(* Logix 5000 project; controller SpectraLink_Test_v2 vendor 1 type 14 code 92 rev 36.12; software revision 36.00 *)

TASK MainTask (continuous, watchdog 500 ms) : MainProgram

MODULES
   Local : vendor 1 type 14 code 92 (ICP 0, rev 36.12)
      ENBT : 1756-ENBT (ICP 1, Ethernet 192.168.3.50, rev 6.1)
         SpectraLink : ETHERNET-MODULE (Ethernet 192.168.3.1, rev 1.1, Output RPI 20 ms)
END_MODULES

TYPE DUT_NDSN_spLink :   // UDDT that holds the Cyclic and ACyclic data for the SpectraLink.
STRUCT
   b_r_LostComm : BOOL;
   b_r_PLC_CommReadOnly : BOOL;
   b_r_SystemReady : BOOL;   // Pattern Status Word 0 Bit 0
   b_r_Fault : BOOL;   // Pattern Status Word 0 Bit 1
   b_r_Alert : BOOL;   // Pattern Status Word 0 Bit 2
   b_r_Commissioned : BOOL;   // Pattern Status Word 0 Bit 3
   b_r_RecipeModified : BOOL;   // Pattern Status Word 0 Bit 5
   i_r_Recipe : INT;
   i_r_PalletizedCount : INT;
   i_r_PalletizedSkipCount : INT;
   di_r_App_Trig_ProductCount : DINT;
   di_r_FeedCount : DINT;
   di_r_DeliveryCount : DINT;
   st_r_AppStat : DUT_NDSN_spLink_Chan_Status[8];
   st_r_TrigStat : DUT_NDSN_spLink_Trig_Status[8];
   st_r_EncoStat : DUT_NDSN_spLink_Encoder_Status[8];
   i_r_ProductLength : DINT[8];
   i_r_ProdRate : INT;
   i_r_LineSpeed : INT[2];   // m/min units
   i_r_RunupOutput : INT[2];
   b_w_UnitEnable : BOOL;   // Pattern Control Word 0 Bit 0
   b_w_ClearAllAlarms : BOOL;   // Clear all System Faults and Alerts (Rising Edge).
   b_w_ResetAllCounters : BOOL;   // Reset all counters (rising edge).
   i_w_LoadRecipe : INT;
   i_w_PalletizedCount : INT;   // Write 0 to decrement; 1 to increment; 2 to reset; else does nothing.
   i_w_PalletizedSkipCount : INT;   // Write 0 to decrement; 1 to increment; 2 to reset; else does nothing.
   di_w_App_Trig_ProductCount : DINT;
   di_w_FeedCountReset : DINT;
   di_w_DeliveryCountReset : DINT;
   st_w_AppCtl : DUT_NDSN_spLink_Chan_CTL[8];
   st_rw_BeadAgg : DUT_NDSN_spLink_Bead[8];
   i_rw_RnUpPercentOutP1 : INT[2];
   i_rw_RnUpLineSpdP1 : INT[2];
   i_rw_RnUpPercentOutP2 : INT[2];
   i_rw_RnUpLineSpdP2 : INT[2];
   i_rw_RnUpLowLim : INT[2];
   i_rw_RnUpHighLim : INT[2];
   di_rw_EncoderRes : DINT[2];
   i_rw_TriggerMaskDist : DINT[8];
   i_rw_TriggerChCtl : INT[8];
   i_rw_EncoderChCtl : INT[2];
   i_rw_RandAdjStart : INT[8];
   i_rw_RandAdjEnd : INT[8];
   i_rw_VirtualTriggerSize : DINT[8];
   i_rw_ContStartSpeed : INT[8];
   i_rw_ContStopSpeed : INT[8];
   i_rw_ContKnifeCutDelay : DINT[8];
   i_rw_ContKnifeCutGap : DINT[8];
   di_rw_GTO : DINT[8];
   i_r_ErrorInfo : INT[4];
   i_r_SpecCtl : INT[4];
   i_r_CurrentFault : INT;
END_STRUCT
END_TYPE

TYPE DUT_NDSN_spLink_Bead :
STRUCT
   di_rw_NumOfBeads : DINT;
   di_rw_BeadDelay : DINT[8];   // 1/4 mm
   di_rw_BeadDuration : DINT[8];   // 1/4 mm
   di_rw_mode : DINT;   // 1/4 mm
   di_rw_MaxGunTime : DINT;   // microseconds
   di_rw_LineSpeedActivation : DINT;   // 100th m/min
   di_rw_LineSpeedDeactivation : DINT;   // 100th m/min
   di_rw_Interval : DINT;   // 1/4 mm
   di_rw_AdhesiveSavings : DINT;   // 30%-60%
   di_rw_EcoBeadPattern : DINT;   // 0-40, Illegal values: 0,1,11,20,21,30,31,38,39
END_STRUCT
END_TYPE

TYPE DUT_NDSN_spLink_Chan_CTL :
STRUCT
   b_w_Enable : BOOL;
   b_w_Purge : BOOL;
END_STRUCT
END_TYPE

TYPE DUT_NDSN_spLink_Chan_Status :
STRUCT
   b_r_Enabled : BOOL;
   b_r_Fault : BOOL;
   b_r_Alert : BOOL;
   b_r_Output_Active : BOOL;
   b_r_Installed : BOOL;
END_STRUCT
END_TYPE

TYPE DUT_NDSN_spLink_Encoder_Status :   // SpectraLink Encoder Channel Status
STRUCT
   b_r_Missing : BOOL;
   b_r_Phase_Missing : BOOL;
   b_r_Scaled : BOOL;
   b_r_Fault : BOOL;
   b_r_Alert : BOOL;
   b_r_Installed : BOOL;
END_STRUCT
END_TYPE

TYPE DUT_NDSN_spLink_HMI_Data :
STRUCT
   r_w_RunUp_1_P1_LineSpeed : REAL;
   r_w_RunUp_2_P1_LineSpeed : REAL;
   r_w_RunUp_1_P2_LineSpeed : REAL;
   r_w_RunUp_2_P2_LineSpeed : REAL;
   r_tempstorage : REAL[4];
   i_tempstorage : INT[4];
END_STRUCT
END_TYPE

TYPE DUT_NDSN_spLink_Rd_Wt :
STRUCT
   i_arr_ReadValue : INT[60];
   i_ReadADI : INT;
   b_ReadDone : BOOL;
   i_arr_WriteValue : INT[60];
   i_WriteADI : INT;
   i_WriteSizeBytes : INT;
   b_WriteEvent : BOOL;
   b_WriteDone : BOOL;
   b_FirstScan : BOOL;
   b_AllowWrites : BOOL;
   b_WriteErr : BOOL;
   b_ReadErr : BOOL;
END_STRUCT
END_TYPE

TYPE DUT_NDSN_spLink_Trig_Status :   // SpectraLink Trigger Channel Status
STRUCT
   b_r_Detected : BOOL;
   b_r_Fault : BOOL;
   b_r_Alert : BOOL;
   b_r_Active : BOOL;
   b_r_Installed : BOOL;
END_STRUCT
END_TYPE

TYPE DUT_spLink_ADI :
STRUCT
   i_ADI : INT;
   i_Size : INT;
END_STRUCT
END_TYPE

ADD_ON_INSTRUCTION AOI_Add_Quad_Resolution   (* revision 1.0 *)
// Raw data from the SpectraLink has a x4 factor included for resolution.  This ADI adds that factor for the SpectraLink.
VAR_IN_OUT
   Bead_Agg : DUT_NDSN_spLink_Bead; {required}
END_VAR
VAR_INPUT
   i_Counter : INT; {access Read Only}
END_VAR

ROUTINE Logic   (* structured text *)
// Raw data from the SpectraLink has a x4 factor included for resolution.  This ADI removes that factor to make editing easier.
   //
   //
   
   FOR i_Counter := 0 TO 7 DO
   
   	Bead_Agg.di_rw_BeadDelay[i_Counter] := Bead_Agg.di_rw_BeadDelay[i_Counter]*4;
   	Bead_Agg.di_rw_BeadDuration[i_Counter] := Bead_Agg.di_rw_BeadDuration[i_Counter]*4;
   
   END_FOR;
END_ROUTINE
END_ADD_ON_INSTRUCTION

ADD_ON_INSTRUCTION AOI_Bead_Calculate_Limits   (* revision 1.0 *)
VAR_IN_OUT
   UDDT1 : DUT_NDSN_spLink_Bead; {required}
   di_DelayHi : DINT[8]; {required}
   di_DelayLo : DINT[8]; {required}
   di_DurHi : DINT[8]; {required}
   di_DurLo : DINT[8]; {required}
END_VAR
VAR_INPUT
   b_time_distance_Mode : BOOL; {access Read Only, required}   // Time
END_VAR
VAR_IN_OUT
   i_DotIntervalHi : DINT; {required}
   i_DotIntervalLo : DINT; {required}
END_VAR
VAR
   Max_Hi_Limit : DINT; {access None}
   i_Counter : INT; {access None}
   i_BeadTemp : INT; {access None}
   DotIntHiLimit : INT; {access None}
   DotIntLoLimit : INT; {access None}
END_VAR

ROUTINE Logic   (* structured text *)
   //****************************************************************************************
   //
   //  Subroutine:  Bead_Calculate_Limits
   //
   //  Function:  Calculate the Bead Edit Low and Hi limits for the Delay and Duration.
   //
   //***************************************************************************************
   
   
   //  Init Code
   //
   
   	If (b_time_distance_Mode) Then
   		Max_Hi_Limit := 10000;
   		i_DotIntervalHi := 1000;
   		i_DotIntervalLo := 2;
   	else
   		Max_Hi_Limit := 99999;
   		i_DotIntervalHi := 99999;
   		i_DotIntervalLo := 5;
   	end_if;
   
   	i_BeadTemp := UDDT1.di_rw_NumOfBeads-1;
   
   //
   	FOR i_Counter := 0 TO 7 DO
   
   		If (i_Counter = 0) then			// Special starting Conditions for Lower Delay Limit and High Duration Limit
   			di_DelayLo[i_Counter] := 	0;
   			di_DelayHi[i_Counter] := 	UDDT1.di_rw_BeadDelay[i_Counter + 1] - UDDT1.di_rw_BeadDuration[i_Counter] - 1;
   			di_DurHi[i_Counter] := 		UDDT1.di_rw_BeadDelay[i_Counter + 1] - UDDT1.di_rw_BeadDelay[i_Counter] - 1;
   			di_DurLo[i_Counter] := 		1;			//  ALL Duration Low Limits are set to 1
   		end_if;
   
   		If ((i_Counter < i_BeadTemp) AND (i_Counter > 0)) then
   			di_DelayLo[i_Counter] := 	UDDT1.di_rw_BeadDelay[i_Counter-1] + UDDT1.di_rw_BeadDuration[i_Counter-1] + 1;
   			di_DelayHi[i_Counter] := 	UDDT1.di_rw_BeadDelay[i_Counter + 1] - UDDT1.di_rw_BeadDuration[i_Counter] - 1;
   			di_DurHi[i_Counter] := 		UDDT1.di_rw_BeadDelay[i_Counter + 1] - UDDT1.di_rw_BeadDelay[i_Counter]  - 1;
   			di_DurLo[i_Counter] := 		1;			//  ALL Duration Low Limits are set to 1
   		end_if;
   
   		if ((i_Counter = i_BeadTemp) AND (i_Counter > 0)) then
   			di_DelayLo[i_Counter] := 	UDDT1.di_rw_BeadDelay[i_Counter-1] + UDDT1.di_rw_BeadDuration[i_Counter-1] + 1;
   			di_DelayHi[i_Counter] := 	Max_Hi_Limit;
   			di_DurHi[i_Counter] := 		Max_Hi_Limit;
   			di_DurLo[i_Counter] := 		1;			//  ALL Duration Low Limits are set to 1
   		end_if;
   
   		if ((i_Counter = i_BeadTemp) AND (i_Counter = 0)) then
   			di_DelayLo[i_Counter] := 	0;
   			di_DelayHi[i_Counter] := 	Max_Hi_Limit;
   			di_DurHi[i_Counter] := 		Max_Hi_Limit;
   			di_DurLo[i_Counter] := 		1;			//  ALL Duration Low Limits are set to 1
   		end_if;
   
   		if (i_Counter > i_BeadTemp) then
   			di_DelayLo[i_Counter] := 	0;
   			di_DelayHi[i_Counter] := 	0;
   			di_DurHi[i_Counter] := 		0;
   			di_DurLo[i_Counter] := 		0;
   		end_if;
   
   
   	END_FOR;
END_ROUTINE
END_ADD_ON_INSTRUCTION

ADD_ON_INSTRUCTION AOI_Remove_Quad_Resolution   (* revision 1.0 *)
// Raw data from the SpectraLink has a x4 factor included for resolution.  This ADI removes that factor to make editing easier.
VAR_IN_OUT
   Bead_Agg : DUT_NDSN_spLink_Bead; {required}
END_VAR
VAR_INPUT
   i_Counter : INT; {access Read Only}
END_VAR

ROUTINE Logic   (* structured text *)
// Raw data from the SpectraLink has a x4 factor included for resolution.  This ADI removes that factor to make editing easier.
   //
   //
   
   FOR i_Counter := 0 TO 7 DO
   
   	Bead_Agg.di_rw_BeadDelay[i_Counter] := Bead_Agg.di_rw_BeadDelay[i_Counter]/4;
   	Bead_Agg.di_rw_BeadDuration[i_Counter] := Bead_Agg.di_rw_BeadDuration[i_Counter]/4;
   
   END_FOR;
END_ROUTINE
END_ADD_ON_INSTRUCTION

ADD_ON_INSTRUCTION AOI_spLink   (* revision 1.0 *)
// AOI to handle the I/O based data (Default Data) and Acyclic Data (low Priority) from the SpectraLink Pattern Controller.
VAR_IN_OUT
   IO_Input : INT[64]; {required}
   IO_Out : INT[64]; {required}
   spLink_HMI : DUT_NDSN_spLink; {required}
   IO_AcycRdWt : DUT_NDSN_spLink_Rd_Wt; {required}
   ReadMsg : MESSAGE; {required}
   WriteMsg : MESSAGE; {required}
   Read_Buffer : INT[100]; {required}
   Write_Buffer : INT[100]; {required}
END_VAR
VAR
   st_ADI_List : DUT_spLink_ADI[40]; {access None}
   tm_Command : FBD_TIMER; {access None}
   tm_Acyc : FBD_TIMER; {access None}
   b_AdhesiveOn : BOOL; {access None}
   b_AdhesiveOff : BOOL; {access None}
   b_Read : BOOL; {access None}
   i_ADI_Range : INT; {access None}
   i_ADI_Size : INT := 20; {access None}
   i_CompareIndex : INT; {access None}
   i_Index : INT; {access None}
   i_Index_Write : INT; {access None}
   i_rwADI_Count : INT := 12; {access None}
   i_rwDataSize : INT := 24; {access None}
   i_Size : INT; {access None}
   i_SizeofStruct : INT := 48; {access None}
   i_ValueIndex : INT; {access None}
   i : INT; {access None}
   i_temp_CPC : INT; {access None}
   arr_WriteIndex : DINT[40]; {access None}
   arr_WriteStartingAddress : DINT[40]; {access None}
   b_AcycWT_Rising : BOOL; {access None}
   arr_HMI : INT[600]; {access None}
   arr_HMI_Buffer : INT[600]; {access None}
   arr_HMI_Compare : INT[600]; {access None}
   b_AcycRD_Rising : BOOL; {access None}
   b_CommandRising : BOOL; {access None}
   tm_PalletizedCount_Reset : FBD_TIMER; {access None}
   b_ResetCurrentPalletizedCount : BOOL; {access None}
   b_ResetCurrentPalletizedSkipCount : BOOL; {access None}
   tm_PalletizedSkipCount_Reset : FBD_TIMER; {access None}
   i_temp_CPSC : INT; {access None}
   i_LoopCnt : INT; {access None}
   b_ResetSelectCount : BOOL; {access None}
   tm_ResetSelectCount : FBD_TIMER := (PRE := 5000); {access None}
   TRUE : BOOL := 1; {access None}
   FALSE : BOOL; {access None}
   tm_ResetFeedCount : FBD_TIMER; {access None}
   tm_ResetDeliveryCount : FBD_TIMER; {access None}
   i_WriteSizeTemp : INT; {access None}
   i_ReadADI_Temp : INT; {access None}
   tm_WriteEvent : FBD_TIMER; {access None}
   b_WriteEventONS : BOOL; {access None}
   i_WritePtr : DINT; {access None}
   Read_Watchdog : FBD_TIMER; {access None}
   Read_Time_Tic : FBD_TIMER; {access None}
   DINT_TEMP : DINT; {access None}
   DINT_Offset : INT; {access Read Only}
END_VAR

ROUTINE Logic   (* structured text *)
   //
   //		SpectraLink Add-On Instruction used to read/write Cyclic (high priority I/O)
   //		and Acyclic (low priority) data.
   //
   //
   //*******************************************************************************
   //	Initialize Code
   //*******************************************************************************
   
   IF IO_AcycRdWt.b_FirstScan THEN
   	i_ADI_Size:= 29;
   	i_rwADI_Count :=26;
   	i_SizeofStruct := 531;
   	i_rwDataSize := 522;
   	i_ADI_Range := 0;
   	i_ValueIndex :=0;
   	i_Index:=0;
   	IO_AcycRdWt.b_FirstScan := 0;		//Reset the FirstScan bit sent to the ADI from the main routine.
   	IO_AcycRdWt.b_AllowWrites := 0;		//Cycle through the full Read Data Set before allowing Writes to occur.  This populates the write compare buffers.
   
   	FOR i := 0 TO i_rwADI_Count DO
   		i_ADI_Range := i_ADI_Range + st_ADI_List[i].i_Size;
   		arr_WriteIndex[i] := i_ADI_Range;					//Index of all Read/Write ADI
   		arr_WriteStartingAddress[i + 1] := i_ADI_Range;		//All Read/Write ADI Starting Address
   	END_FOR;
   
   
   END_IF;
   
   
   
   
   //*******************************************************************************
   //  Start of Cyclic Data Code
   //
   //	The following code handles the I/O data for the High Priority DEFAULT ADIs.
   //*******************************************************************************
   
   // SpectraLink system Status
   spLink_HMI.b_r_SystemReady := IO_Input[0].0;
   spLink_HMI.b_r_Fault := IO_Input[0].1;
   spLink_HMI.b_r_Alert := IO_Input[0].2;
   spLink_HMI.b_r_Commissioned := IO_Input[0].3;
   spLink_HMI.b_r_PLC_CommReadOnly := IO_Input[0].4;
   spLink_HMI.b_r_RecipeModified := IO_Input[0].5;
   
   spLink_HMI.i_r_Recipe := IO_Input[4];
   spLink_HMI.i_r_PalletizedCount := IO_Input[5];
   spLink_HMI.i_r_PalletizedSkipCount := IO_Input[6];
   
   COP(IO_Input[7], spLink_HMI.di_r_App_Trig_ProductCount, 6);
   
   // Copy the Applicator Status Structure Bits from the IO_Inputs
   i_LoopCnt := 0;
   While (i_LoopCnt < 8) DO
   	spLink_HMI.st_r_AppStat[i_LoopCnt].b_r_Enabled := IO_Input[13+i_LoopCnt].0;
   	spLink_HMI.st_r_AppStat[i_LoopCnt].b_r_Fault := IO_Input[13+i_LoopCnt].1;
   	spLink_HMI.st_r_AppStat[i_LoopCnt].b_r_Alert := IO_Input[13+i_LoopCnt].2;
   	spLink_HMI.st_r_AppStat[i_LoopCnt].b_r_Output_Active := IO_Input[13+i_LoopCnt].3;
   	spLink_HMI.st_r_AppStat[i_LoopCnt].b_r_Installed := IO_Input[13+i_LoopCnt].4;
   	i_LoopCnt := i_LoopCnt+1;
   end_while;
   
   // Copy the Trigger Status Structure Bits from the IO_Inputs
   i_LoopCnt := 0;
   While (i_LoopCnt < 8) DO
   	spLink_HMI.st_r_TrigStat[i_LoopCnt].b_r_Detected := IO_Input[21+i_LoopCnt].0;
   	spLink_HMI.st_r_TrigStat[i_LoopCnt].b_r_Fault := IO_Input[21+i_LoopCnt].1;
   	spLink_HMI.st_r_TrigStat[i_LoopCnt].b_r_Alert := IO_Input[21+i_LoopCnt].2;
   	spLink_HMI.st_r_TrigStat[i_LoopCnt].b_r_Active := IO_Input[21+i_LoopCnt].3;
   	i_LoopCnt := i_LoopCnt+1;
   end_while;
   
   // Copy the Encoder Status Structure Bits from the IO_Inputs
   i_LoopCnt := 0;
   While (i_LoopCnt < 2) DO
   	spLink_HMI.st_r_EncoStat[i_LoopCnt].b_r_Missing := IO_Input[29+i_LoopCnt].0;
   	spLink_HMI.st_r_EncoStat[i_LoopCnt].b_r_Phase_Missing := IO_Input[29+i_LoopCnt].1;
   	spLink_HMI.st_r_EncoStat[i_LoopCnt].b_r_Scaled := IO_Input[29+i_LoopCnt].2;
   	spLink_HMI.st_r_EncoStat[i_LoopCnt].b_r_Fault := IO_Input[29+i_LoopCnt].3;
   	spLink_HMI.st_r_EncoStat[i_LoopCnt].b_r_Alert := IO_Input[29+i_LoopCnt].4;
   	i_LoopCnt := i_LoopCnt+1;
   end_while;
   
   
   //******************************************************************************************************************
   //Adjust the Product Length by a factor of 4
   //******************************************************************************************************************
   
   i_LoopCnt := 0;
   While (i_LoopCnt < 8) DO
   	DINT_Offset := i_LoopCnt*2;
   	COP(IO_Input[31+DINT_Offset], DINT_TEMP, 2);
   	spLink_HMI.i_r_ProductLength[i_LoopCnt] := (DINT_TEMP/4);
   	i_LoopCnt := i_LoopCnt+1;
   end_while;
   
   
   COP(IO_Input[47], spLink_HMI.i_r_ProdRate, 1);
   COP(IO_Input[48], spLink_HMI.i_r_LineSpeed[0], 2);
   COP(IO_Input[50], spLink_HMI.i_r_RunupOutput[0], 2);
   
   
   //******************************************************************************************************************
   //Cyclic WRITE Section
   //******************************************************************************************************************
   
   IO_Out[0].0 := spLink_HMI.b_w_UnitEnable;
   IO_Out[2].0 := spLink_HMI.b_w_ClearAllAlarms;
   IO_Out[2].1 := spLink_HMI.b_w_ResetAllCounters;
   
   IO_Out[4] := spLink_HMI.i_w_LoadRecipe;
   
   
   //********************************************************************************************************************************
   //Current Palatized Count & Current Palatized Skip Count     increment (1) or decrement (0);  else = other value     (ADI 16359 Write)
   //********************************************************************************************************************************
   //*********************************************************************
   //PLC logic will set the increment flag (1) or the decrement flag (0) which will generate a 1 second pulse to the spLink.  The
   //command must be set to a "else value" before another increment or decrement can occur.
   //*********************************************************************
   
   IF (spLink_HMI.i_w_PalletizedCount <> i_temp_CPC) AND NOT tm_PalletizedCount_Reset.EN AND NOT b_ResetCurrentPalletizedCount then
   	b_ResetCurrentPalletizedCount := 1;
   	i_temp_CPC := spLink_HMI.i_w_PalletizedCount;
   	tm_PalletizedCount_Reset.Reset := NOT b_ResetCurrentPalletizedCount;
   end_if;
   
   tm_PalletizedCount_Reset.PRE :=2000;
   tm_PalletizedCount_Reset.TimerEnable := b_ResetCurrentPalletizedCount;
   TONR(tm_PalletizedCount_Reset);
   
   If tm_PalletizedCount_Reset.DN then
   	b_ResetCurrentPalletizedCount := 0;
   end_if;
   
   
   IF (tm_PalletizedCount_Reset.EN AND NOT tm_PalletizedCount_Reset.DN AND (i_temp_CPC = 0)) then
   	IO_Out[5] := 0;
   elsif (tm_PalletizedCount_Reset.EN AND NOT tm_PalletizedCount_Reset.DN AND (i_temp_CPC = 1)) then
   	IO_Out[5] := 1;
   else
   	IO_Out[5] := 5;  // anything but a 1 or 0
   end_if;
   
   
   IF (spLink_HMI.i_w_PalletizedSkipCount <> i_temp_CPSC) AND NOT tm_PalletizedSkipCount_Reset.EN AND NOT b_ResetCurrentPalletizedSkipCount then
   	b_ResetCurrentPalletizedSkipCount := 1;
   	i_temp_CPSC := spLink_HMI.i_w_PalletizedSkipCount;
   	tm_PalletizedCount_Reset.Reset := NOT b_ResetCurrentPalletizedSkipCount;
   end_if;
   
   tm_PalletizedSkipCount_Reset.PRE :=2000;
   tm_PalletizedSkipCount_Reset.TimerEnable := b_ResetCurrentPalletizedSkipCount;
   TONR(tm_PalletizedSkipCount_Reset);
   
   IF (tm_PalletizedSkipCount_Reset.EN AND NOT tm_PalletizedSkipCount_Reset.DN AND (i_temp_CPSC = 0)) then
   	IO_Out[6] := 0;
   elsif (tm_PalletizedSkipCount_Reset.EN AND NOT tm_PalletizedSkipCount_Reset.DN AND (i_temp_CPSC = 1)) then
   	IO_Out[6] := 1;
   else
   	IO_Out[6] := 5;  // anything but a 1 or 0
   end_if;
   
   
   If tm_PalletizedSkipCount_Reset.DN then
   	b_ResetCurrentPalletizedSkipCount := 0;
   end_if;
   
   
   //********************************************************************************************************************************
   //Display Select Count, Feed Count and Delivery Count Reset     reset (1) or do nothing (0);        (ADI 16656 Write)
   //********************************************************************************************************************************
   //*********************************************************************
   //PLC logic will set the Reset (1) which will generate a 1 second pulse to the spLink.  The
   //command must be set to a "0" before another Reset can occur.
   //*********************************************************************
   
   
   	tm_ResetSelectCount.PRE := 1000;
   	tm_ResetSelectCount.TimerEnable := spLink_HMI.di_w_App_Trig_ProductCount.0;
   	tm_ResetSelectCount.Reset := NOT spLink_HMI.di_w_App_Trig_ProductCount.0;
   	TONR(tm_ResetSelectCount);
   
   	IF tm_ResetSelectCount.TT then
   		IO_Out[7] := 1;
   	else
   		IO_Out[7] := 0;
   	end_if;
   
   
   	tm_ResetFeedCount.PRE := 1000;
   	tm_ResetFeedCount.TimerEnable := spLink_HMI.di_w_FeedCountReset.0;
   	tm_ResetFeedCount.Reset := NOT spLink_HMI.di_w_FeedCountReset.0;
   	TONR(tm_ResetFeedCount);
   
   	IF tm_ResetFeedCount.TT then
   		IO_Out[9] := 1;
   	else
   		IO_Out[9] := 0;
   	end_if;
   
   
   	tm_ResetDeliveryCount.PRE := 1000;
   	tm_ResetDeliveryCount.TimerEnable := spLink_HMI.di_w_DeliveryCountReset.0;
   	tm_ResetDeliveryCount.Reset := NOT spLink_HMI.di_w_DeliveryCountReset.0;
   	TONR(tm_ResetDeliveryCount);
   
   	IF tm_ResetDeliveryCount.TT then
   		IO_Out[11] := 1;
   	else
   		IO_Out[11] := 0;
   	end_if;
   
   
   //********************************************************************************************************************************
   //Send the Applicator Channel Control Aggregate data to the PC.       (ADI 18675 Write)
   //********************************************************************************************************************************
   
   	i_LoopCnt := 0;
   While (i_LoopCnt < 8) DO
   	IO_Out[13+i_LoopCnt].0 := spLink_HMI.st_w_AppCtl[i_LoopCnt].b_w_Enable;
   	IO_Out[13+i_LoopCnt].1 := spLink_HMI.st_w_AppCtl[i_LoopCnt].b_w_Purge;
   	i_LoopCnt := i_LoopCnt+1;
   end_while;
   
   
   //*******************************************************************************************************************************
   //  Start of Acyclic Data Code
   //
   //	The following code handles the Explicit Messages for the Lower Priority ADIs.
   //*******************************************************************************
   
   tm_Acyc.PRE :=350;
   tm_Acyc.TimerEnable := NOT b_Read AND NOT IO_AcycRdWt.b_WriteEvent;
   TONR(tm_Acyc);
   b_Read :=tm_Acyc.DN;
   
   //Read Message Time Tic (25mSec between Reads)
   
   Read_Time_Tic.PRE := 25;
   Read_Time_Tic.TimerEnable := NOT Read_Time_Tic.DN;
   TONR(Read_Time_Tic);
   
   
   //Read Message Watchdog
   
   Read_Watchdog.PRE :=500;
   Read_Watchdog.TimerEnable := NOT Read_Watchdog.DN;
   TONR(Read_Watchdog);
   Read_Watchdog.Reset := 0;
   
   If Read_Watchdog.DN then
   	i_ReadADI_Temp  := 0;
   
   end_if;
   
   
   //******************************************************************
   //Sequentially read ALL ADIs and store into structure
   //b_read will initiate when tm_Acyc Expired,b_AcycRD_Tick will
   //trigger the funciton block when read is done,
   //b_AcycRD_Enable only last during Acyclic reading in process
   //When last ADI been read, it will stop reading until next cycle
   //*******************************************************************
   IO_AcycRdWt.i_ReadADI := st_ADI_List[i_Index].i_ADI;
   i_Size := st_ADI_List[i_Index].i_Size;
   
   
   If (IO_AcycRdWt.i_ReadADI <> i_ReadADI_Temp) AND Read_Time_Tic.DN then
   
   	ReadMsg.Instance := IO_AcycRdWt.i_ReadADI;
   	MSG(ReadMsg);
   	i_ReadADI_Temp := IO_AcycRdWt.i_ReadADI;
   
   end_if;
   
   IO_AcycRdWt.b_ReadDone := ReadMsg.DN;
   IO_AcycRdWt.b_ReadErr := ReadMsg.ER;
   
   IF IO_AcycRdWt.b_ReadDone AND NOT IO_AcycRdWt.b_WriteEvent AND b_AcycRD_Rising THEN
   
   	COP(Read_Buffer[0],arr_HMI[i_ValueIndex],i_Size);
   
   	//****************************************************
   	//After reading the current ADI, index to next one
   	//****************************************************
   	i_ValueIndex := i_ValueIndex + st_ADI_List[i_Index].i_Size;
       i_Index := i_Index + 1;
   
   	Read_Watchdog.Reset := 1;
   
   END_IF;
   
   b_AcycRD_Rising := NOT IO_AcycRdWt.b_ReadDone;
   
   
   //****************************************************
   //Copy all reading value into structure
   //****************************************************
   IF b_Read THEN
   	COP(arr_HMI[0],spLink_HMI.st_rw_BeadAgg[0],i_SizeofStruct);
   	COP(arr_HMI[0],arr_HMI_Buffer[0],i_rwDataSize);
   END_IF;
   
   IF ((i_Index = i_ADI_Size) AND b_Read) THEN
       i_Index := 0;
   	i_ValueIndex :=0;
   	IO_AcycRdWt.b_AllowWrites := 1;
   END_IF;
   
   //**********************************************************************************************
   //Copy all read/write ADI reading into arr_HMI_Buffer_Compare for further generating Write Event
   //***********************************************************************************************
   COP(spLink_HMI.st_rw_BeadAgg[0],arr_HMI_Compare[0],i_rwDataSize);
   
   //**************************************************************************************
   //Compare arr_HMI_Compare with arr_HMI_Buffer to generate write event
   //**************************************************************************************
   tm_WriteEvent.PRE :=350;
   tm_WriteEvent.TimerEnable :=IO_AcycRdWt.b_WriteEvent;
   TONR(tm_WriteEvent);
   
   
   b_WriteEventONS := 0;
   
   FOR i:=0 TO i_rwDataSize-1 BY 1 DO
   	IF (arr_HMI_Compare[i] <> arr_HMI_Buffer[i]) AND NOT IO_AcycRdWt.b_WriteEvent and IO_AcycRdWt.b_AllowWrites THEN
   
   		i_CompareIndex := i;
   		IO_AcycRdWt.b_WriteEvent := 1;
   		b_WriteEventONS := 1;
   		arr_HMI_Buffer[i] :=arr_HMI_Compare[i];
   
   		EXIT;
   	END_IF;
   END_FOR;
   
   IF b_WriteEventONS THEN
   	//***************************************************************
   	//When write event locate the write index inside arr_WriteIndex
   	//***************************************************************
       FOR i := 0 TO i_rwADI_Count DO
           IF i_CompareIndex < arr_WriteIndex[i] THEN
               i_Index_Write := i;
               EXIT;
           END_IF;
       END_FOR;
   
   	i_WriteSizeTemp := st_ADI_List[i_Index_Write].i_Size;
   	IO_AcycRdWt.i_WriteADI := st_ADI_List[i_Index_Write].i_ADI;
   
   	i_WritePtr := arr_WriteStartingAddress[i_Index_Write];
   	COP(arr_HMI_Compare[i_WritePtr],IO_AcycRdWt.i_arr_WriteValue[0],i_WriteSizeTemp);
   	COP(arr_HMI_Compare[i_WritePtr],arr_HMI[i_WritePtr],i_WriteSizeTemp);
   
   	IO_AcycRdWt.i_WriteSizeBytes := i_WriteSizeTemp*2;
   
   	COP(arr_HMI_Compare[i_WritePtr], Write_Buffer[0],i_WriteSizeTemp);
   	WriteMsg.Instance := IO_AcycRdWt.i_WriteADI;
   	WriteMsg.REQ_LEN := IO_AcycRdWt.i_WriteSizeBytes;
   	MSG(WriteMsg);
   
   END_IF;
   
   	IO_AcycRdWt.b_WriteDone := WriteMsg.DN;
   	IO_AcycRdWt.b_WriteErr := WriteMsg.ER;
   
   IF tm_WriteEvent.DN OR (IO_AcycRdWt.b_WriteDone AND b_AcycWT_Rising) THEN
   	IO_AcycRdWt.b_WriteEvent :=0;
   END_IF;
   b_AcycWT_Rising := NOT IO_AcycRdWt.b_WriteDone;
   
   
   
   
   //
   //   NOTES:  After MSG Write is working, go back and add ERR bits to the IO_AcycRdWt UDDT.
   //
   //
   
   
   
END_ROUTINE
END_ADD_ON_INSTRUCTION

ADD_ON_INSTRUCTION AOI_UDDT_Compare   (* revision 1.0 *)
VAR_INPUT
   UDDT_INT_SIZE : DINT; {access Read Only, required}
END_VAR
VAR_IN_OUT
   UDDT_1 : DUT_NDSN_spLink_Bead; {required}
   UDDT_2 : DUT_NDSN_spLink_Bead; {required}
END_VAR
VAR_OUTPUT
   NOT_EQUAL : BOOL; {visible}
   EQUAL : BOOL; {visible}
END_VAR
VAR_INPUT
   i_count : INT; {access Read Only}
END_VAR
VAR
   i_buffer1 : DINT[100]; {access None}
   i_buffer2 : DINT[100]; {access None}
   d_count : INT; {access None}
   d_size : INT; {access None}
END_VAR

ROUTINE Logic   (* structured text *)
   //****************************************************************************************************
   //*****  UDDT Compare
   //*****
   //*****  DESCRIPTION:  Subroutine to compare to UDDTs of equal length.  If a difference is located, the NOT_EQUAL output
   //*****					Bit is set.  Otherwise, the EQUAL Bit is set.
   //*****
   //*****
   
   EQUAL := 1;
   NOT_EQUAL := 0;
   i_count := 0;
   d_size := UDDT_INT_SIZE/2;
   
   COP(UDDT_1.di_rw_NumOfBeads, i_buffer1[0], d_size);
   COP(UDDT_2.di_rw_NumOfBeads, i_buffer2[0], d_size);
   
   
   FOR i_count :=0 TO d_size-1 BY 1 DO
   	IF (i_buffer1[i_count] <> i_buffer2[i_count])  THEN
   
   		EQUAL := 0;
   		NOT_EQUAL := 1;
   		EXIT;
   	END_IF;
   END_FOR;
   
END_ROUTINE
END_ADD_ON_INSTRUCTION

VAR_GLOBAL   (* controller tags *)
   ADI_Temp_Constant : INT := 4;
   b_PView_Edit_PB : BOOL;
   b_PView_EditBeadActive : BOOL;
   b_r_DecrementBeadCh : BOOL;
   b_r_IncrementBeadCh : BOOL;
   b_r_SaveBeadEdits : BOOL;
   Bead_Agg_Temp : DUT_NDSN_spLink_Bead := (di_rw_NumOfBeads := 4, di_rw_BeadDelay[0] := 14, di_rw_BeadDelay[1] := 40, di_rw_BeadDelay[2] := 80, di_rw_BeadDelay[3] := 120, di_rw_BeadDuration[0] := 10, di_rw_BeadDuration[1] := 20, di_rw_BeadDuration[2] := 30, di_rw_BeadDuration[3] := 40, di_rw_mode := 5, di_rw_MaxGunTime := 10000, di_rw_LineSpeedActivation := 500, di_rw_LineSpeedDeactivation := 300, di_rw_Interval := 400, di_rw_AdhesiveSavings := 40, di_rw_EcoBeadPattern := 12);
   BEAD_COMPARE_ADI : AOI_UDDT_Compare := (UDDT_INT_SIZE := 48, NOT_EQUAL := 1, i_count := 1);
   di_r_DelayHiLimit : DINT[8] := ([0] := 29, [1] := 59, [2] := 89, [3] := 10000);
   di_r_DelayLowLimit : DINT[8] := ([1] := 25, [2] := 61, [3] := 111);
   di_r_DurHiLimit : DINT[8] := ([0] := 25, [1] := 39, [2] := 39, [3] := 10000);
   di_r_DurLowLimit : DINT[8] := ([0] := 1, [1] := 1, [2] := 1, [3] := 1);
   i_BeadChannel_Temp : INT;
   i_DotIntervalHi : DINT := 1000;
   i_DotIntervalLo : DINT := 2;
   i_RandomAdjEnd : INT := 40;
   i_RandomAdjEndTemp : INT := 40;
   i_RandomAdjStart : INT := 40;
   i_RandomAdjStartTemp : INT := 40;
   i_rw_BeadChannel : INT;
   msg_AOI_spLink_Read : MESSAGE;
        MessageParameters(ServiceCode := 16#000e, DestinationTag := spLink_MSG_Read_Buffer, ...)
   msg_AOI_spLink_Write : MESSAGE;
        MessageParameters(ServiceCode := 16#0010, LocalElement := spLink_MSG_Write_Buffer[0], ...)
   msgRead_spLink : MESSAGE;
        MessageParameters(ServiceCode := 16#000e, DestinationTag := Test_Read_Array[0], ...)
   msgWrite_spLink : MESSAGE;
        MessageParameters(ServiceCode := 16#0010, LocalElement := ADI_Temp_Constant, ...)
   ons_decrement : BOOL;
   ons_increment : BOOL;
   spLink_AcyRdWt : DUT_NDSN_spLink_Rd_Wt := (i_ReadADI := 16001, b_ReadDone := 1, i_arr_WriteValue[0] := 4, i_arr_WriteValue[2] := 56, i_arr_WriteValue[4] := 160, i_arr_WriteValue[6] := 320, i_arr_WriteValue[8] := 480, i_arr_WriteValue[18] := 40, i_arr_WriteValue[20] := 80, i_arr_WriteValue[22] := 120, i_arr_WriteValue[24] := 160, i_arr_WriteValue[34] := 5, i_arr_WriteValue[36] := 10000, i_arr_WriteValue[38] := 500, i_arr_WriteValue[40] := 300, i_arr_WriteValue[42] := 400, i_arr_WriteValue[44] := 40, i_arr_WriteValue[46] := 12, i_WriteADI := 17076, i_WriteSizeBytes := 96, b_WriteDone := 1, b_AllowWrites := 1);
   spLink_AOI : AOI_spLink;
   spLink_HMI : DUT_NDSN_spLink;
   spLink_HMI_Data : DUT_NDSN_spLink_HMI_Data := (r_w_RunUp_1_P1_LineSpeed := 1.5, r_w_RunUp_1_P2_LineSpeed := 100.0, r_w_RunUp_2_P2_LineSpeed := 100.0, r_tempstorage[0] := 1.5, r_tempstorage[2] := 100.0, r_tempstorage[3] := 100.0, i_tempstorage[0] := 150, i_tempstorage[2] := 10000, i_tempstorage[3] := 10000);
   spLink_MSG_Read_Buffer : INT[100];
   spLink_MSG_Write_Buffer : INT[100] := ([0] := 4, [2] := 56, [4] := 160, [6] := 320, [8] := 480, [18] := 40, [20] := 80, [22] := 120, [24] := 160, [34] := 5, [36] := 10000, [38] := 500, [40] := 300, [42] := 400, [44] := 40, [46] := 12);
   Test_Read_Array : INT[4];
   Test_Read_Data : INT := 4;
END_VAR

PROGRAM MainProgram   (* main routine MainRoutine *)
VAR
   ADI_Add_Quad : AOI_Add_Quad_Resolution := (i_Counter := 8);
   ADI_Calc_Limits : AOI_Bead_Calculate_Limits := (b_time_distance_Mode := 1);
   ADI_Remove_Quad : AOI_Remove_Quad_Resolution := (i_Counter := 8);
   ADI_Remove_Quad2 : AOI_Remove_Quad_Resolution := (i_Counter := 8);
   b_EditBeadTemp : BOOL;
   Bead_Agg_Compare : DUT_NDSN_spLink_Bead := (di_rw_NumOfBeads := 4, di_rw_BeadDelay[0] := 14, di_rw_BeadDelay[1] := 40, di_rw_BeadDelay[2] := 80, di_rw_BeadDelay[3] := 120, di_rw_BeadDuration[0] := 10, di_rw_BeadDuration[1] := 20, di_rw_BeadDuration[2] := 30, di_rw_BeadDuration[3] := 40, di_rw_mode := 5, di_rw_MaxGunTime := 10000, di_rw_LineSpeedActivation := 500, di_rw_LineSpeedDeactivation := 300, di_rw_Interval := 400, di_rw_AdhesiveSavings := 40, di_rw_EcoBeadPattern := 12);
   Bead_Agg_Temp2 : DUT_NDSN_spLink_Bead := (di_rw_NumOfBeads := 4, di_rw_BeadDelay[0] := 56, di_rw_BeadDelay[1] := 160, di_rw_BeadDelay[2] := 320, di_rw_BeadDelay[3] := 480, di_rw_BeadDuration[0] := 40, di_rw_BeadDuration[1] := 80, di_rw_BeadDuration[2] := 120, di_rw_BeadDuration[3] := 160, di_rw_mode := 5, di_rw_MaxGunTime := 10000, di_rw_LineSpeedActivation := 500, di_rw_LineSpeedDeactivation := 300, di_rw_Interval := 400, di_rw_AdhesiveSavings := 40, di_rw_EcoBeadPattern := 12);
   Change_Detected : BOOL;
   EditToggle_ONS : BOOL;
   i_splink_1_Comm : DINT := 16384;
   msgRead_ONS : BOOL;
   msgWrite_ONS : BOOL;
   Read_Temp : INT := 4;
   splink_CommLost_cnt : DINT;
   splink_LostComm_ONS : BOOL;
   Start_ReadMSG : BOOL;
   Start_WriteMSG : BOOL;
   Test_Read_Att : INT := 18100;
   Test_Write_Att : INT := 18100;
   Test_Write_Data : INT := 4;
   tm_spLink_CommStarting : TIMER := (PRE := 5000);
END_VAR

ROUTINE Bead_Edit_Support   (* ladder *)
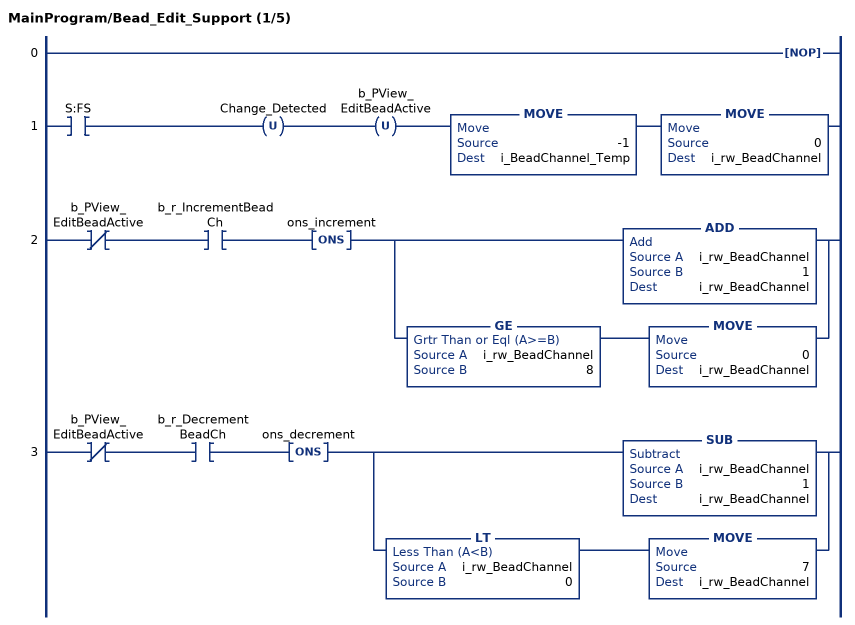
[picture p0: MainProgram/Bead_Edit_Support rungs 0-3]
   0: NOP();
   1: XIC(S:FS)OTU(Change_Detected)OTU(b_PView_EditBeadActive)MOVE(-1,i_BeadChannel_Temp)MOVE(0,i_rw_BeadChannel);
   2: XIO(b_PView_EditBeadActive)XIC(b_r_IncrementBeadCh)ONS(ons_increment)[ADD(i_rw_BeadChannel,1,i_rw_BeadChannel) ,GE(i_rw_BeadChannel,8) MOVE(0,i_rw_BeadChannel) ];
   3: XIO(b_PView_EditBeadActive)XIC(b_r_DecrementBeadCh)ONS(ons_decrement)[SUB(i_rw_BeadChannel,1,i_rw_BeadChannel) ,LT(i_rw_BeadChannel,0) MOVE(7,i_rw_BeadChannel) ];
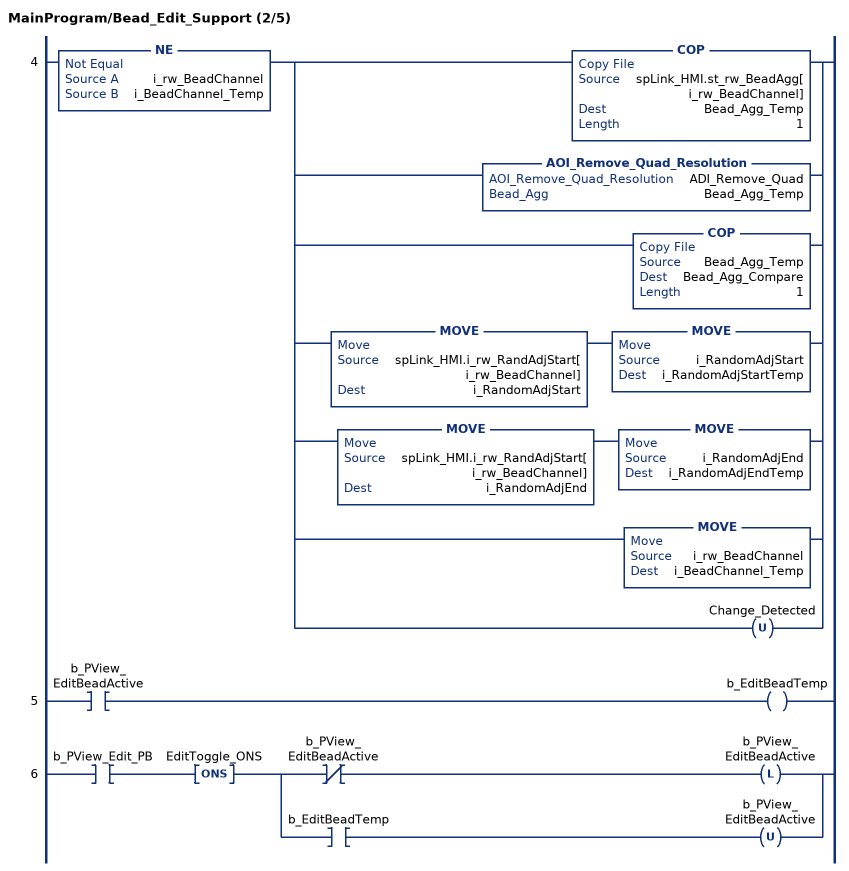
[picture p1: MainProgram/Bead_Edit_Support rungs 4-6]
   4: NE(i_rw_BeadChannel,i_BeadChannel_Temp)[COP(spLink_HMI.st_rw_BeadAgg[ i_rw_BeadChannel],Bead_Agg_Temp,1) ,AOI_Remove_Quad_Resolution(ADI_Remove_Quad,Bead_Agg_Temp) ,COP(Bead_Agg_Temp,Bead_Agg_Compare,1) ,MOVE(spLink_HMI.i_rw_RandAdjStart[i_rw_BeadChannel],i_RandomAdjStart) MOVE(i_RandomAdjStart,i_RandomAdjStartTemp) ,MOVE(spLink_HMI.i_rw_RandAdjStart[i_rw_BeadChannel],i_RandomAdjEnd) MOVE(i_RandomAdjEnd,i_RandomAdjEndTemp) ,MOVE(i_rw_BeadChannel,i_BeadChannel_Temp) ,OTU(Change_Detected) ];
   5: XIC(b_PView_EditBeadActive)OTE(b_EditBeadTemp);
   6: XIC(b_PView_Edit_PB)ONS(EditToggle_ONS)[XIO(b_PView_EditBeadActive) OTL(b_PView_EditBeadActive) ,XIC(b_EditBeadTemp) OTU(b_PView_EditBeadActive) ];
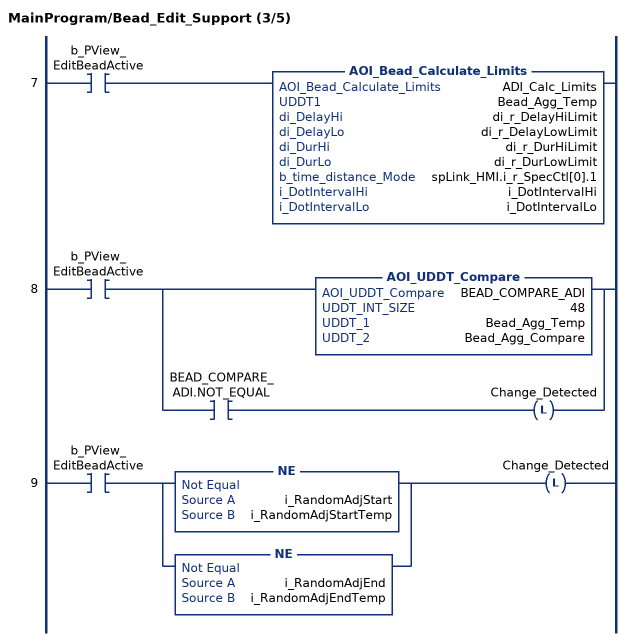
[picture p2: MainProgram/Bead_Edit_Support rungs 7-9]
   7: XIC(b_PView_EditBeadActive)AOI_Bead_Calculate_Limits(ADI_Calc_Limits,Bead_Agg_Temp,di_r_DelayHiLimit,di_r_DelayLowLimit,di_r_DurHiLimit,di_r_DurLowLimit,spLink_HMI.i_r_SpecCtl[0].1,i_DotIntervalHi,i_DotIntervalLo);
   8: XIC(b_PView_EditBeadActive)[AOI_UDDT_Compare(BEAD_COMPARE_ADI,48,Bead_Agg_Temp,Bead_Agg_Compare) ,XIC(BEAD_COMPARE_ADI.NOT_EQUAL) OTL(Change_Detected) ];
   9: XIC(b_PView_EditBeadActive)[NE(i_RandomAdjStart,i_RandomAdjStartTemp) ,NE(i_RandomAdjEnd,i_RandomAdjEndTemp) ]OTL(Change_Detected);
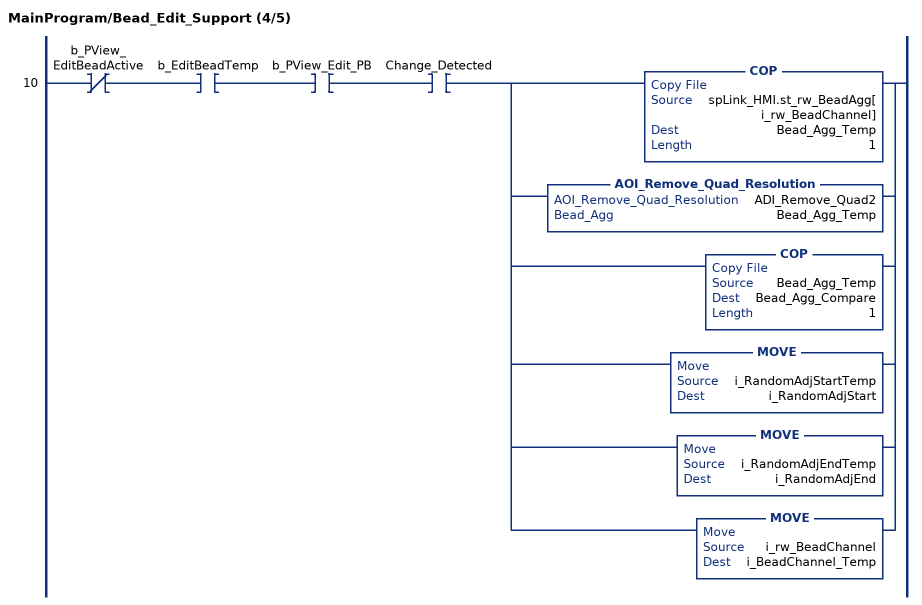
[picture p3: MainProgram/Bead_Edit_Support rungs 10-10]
   10: XIO(b_PView_EditBeadActive)XIC(b_EditBeadTemp)XIC(b_PView_Edit_PB)XIC(Change_Detected)[COP(spLink_HMI.st_rw_BeadAgg[ i_rw_BeadChannel],Bead_Agg_Temp,1) ,AOI_Remove_Quad_Resolution(ADI_Remove_Quad2,Bead_Agg_Temp) ,COP(Bead_Agg_Temp,Bead_Agg_Compare,1) ,MOVE(i_RandomAdjStartTemp,i_RandomAdjStart) ,MOVE(i_RandomAdjEndTemp,i_RandomAdjEnd) ,MOVE(i_rw_BeadChannel,i_BeadChannel_Temp) ];
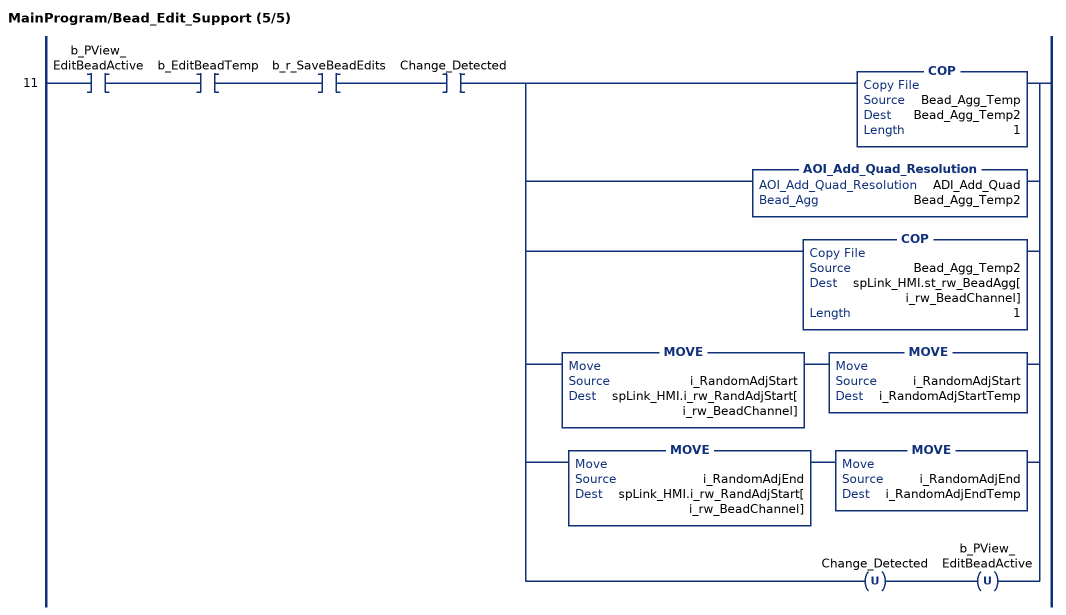
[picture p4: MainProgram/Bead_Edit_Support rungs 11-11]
   11: XIC(b_PView_EditBeadActive)XIC(b_EditBeadTemp)XIC(b_r_SaveBeadEdits)XIC(Change_Detected)[COP(Bead_Agg_Temp,Bead_Agg_Temp2,1) ,AOI_Add_Quad_Resolution(ADI_Add_Quad,Bead_Agg_Temp2) ,COP(Bead_Agg_Temp2,spLink_HMI.st_rw_BeadAgg[ i_rw_BeadChannel],1) ,MOVE(i_RandomAdjStart,spLink_HMI.i_rw_RandAdjStart[i_rw_BeadChannel]) MOVE(i_RandomAdjStart,i_RandomAdjStartTemp) ,MOVE(i_RandomAdjEnd,spLink_HMI.i_rw_RandAdjStart[i_rw_BeadChannel]) MOVE(i_RandomAdjEnd,i_RandomAdjEndTemp) ,OTU(Change_Detected) OTU(b_PView_EditBeadActive) ];
END_ROUTINE

ROUTINE MainRoutine   (* ladder *)
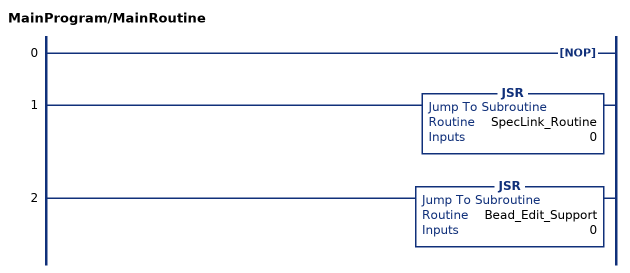
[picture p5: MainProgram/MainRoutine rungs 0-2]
   0: NOP();
   1: JSR(SpecLink_Routine,0);
   2: JSR(Bead_Edit_Support,0);
END_ROUTINE

ROUTINE SpecLink_Routine   (* ladder *)
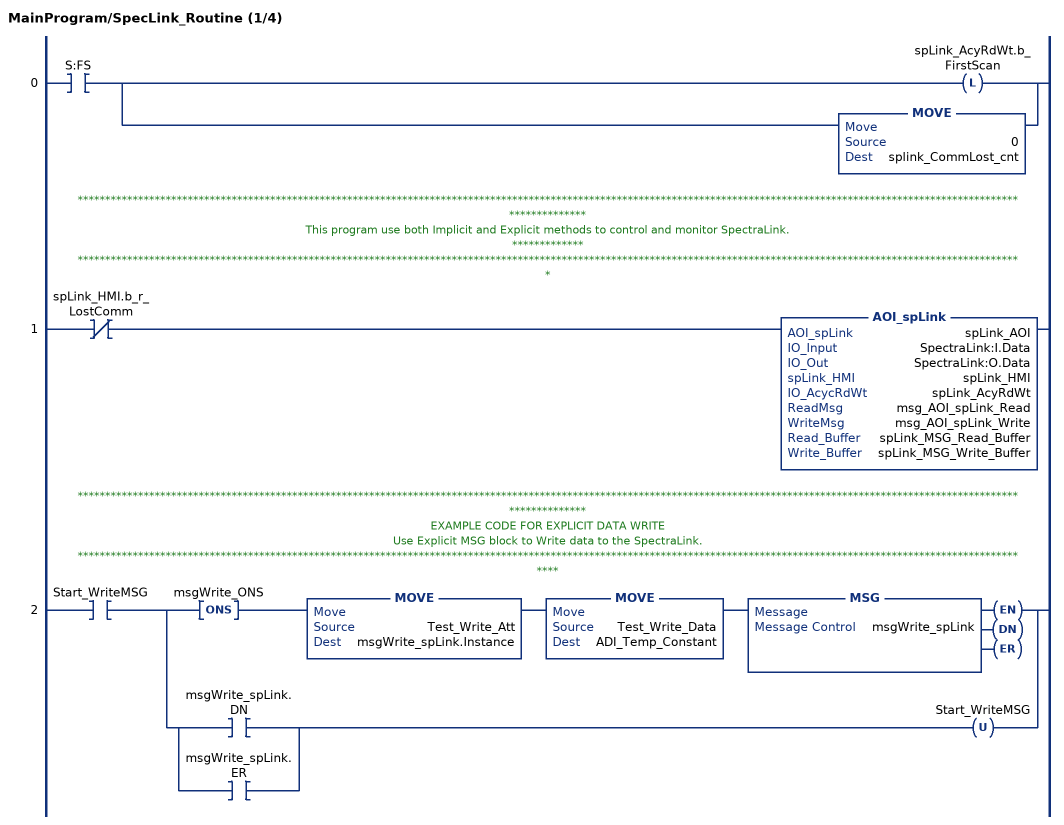
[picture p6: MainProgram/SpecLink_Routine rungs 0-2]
   0: XIC(S:FS)[OTL(spLink_AcyRdWt.b_FirstScan) ,MOVE(0,splink_CommLost_cnt) ];
   // *****************************************************************************************************************************************************************************************
   // This program use both Implicit and Explicit methods to control and monitor SpectraLink.
   // *************
   // ****************************************************************************************************************************************************************************
   1: XIO(spLink_HMI.b_r_LostComm)AOI_spLink(spLink_AOI,SpectraLink:I.Data,SpectraLink:O.Data,spLink_HMI,spLink_AcyRdWt,msg_AOI_spLink_Read,msg_AOI_spLink_Write,spLink_MSG_Read_Buffer,spLink_MSG_Write_Buffer);
   // *****************************************************************************************************************************************************************************************
   // EXAMPLE CODE FOR EXPLICIT DATA WRITE
   // Use Explicit MSG block to Write data to the SpectraLink.
   // *******************************************************************************************************************************************************************************
   2: XIC(Start_WriteMSG)[ONS(msgWrite_ONS) MOVE(Test_Write_Att,msgWrite_spLink.Instance) MOVE(Test_Write_Data,ADI_Temp_Constant) MSG(msgWrite_spLink) ,[XIC(msgWrite_spLink.DN) ,XIC(msgWrite_spLink.ER) ] OTU(Start_WriteMSG) ];
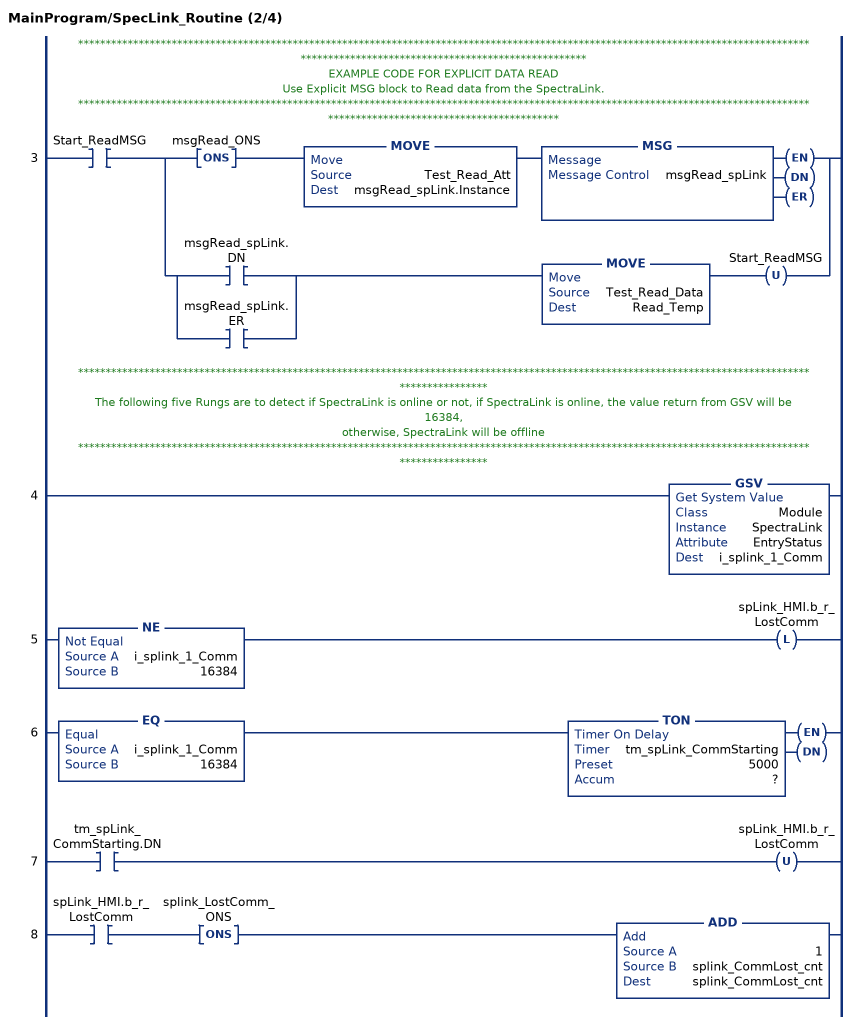
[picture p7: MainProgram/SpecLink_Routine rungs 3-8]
   // *****************************************************************************************************************************************************************************************
   // EXAMPLE CODE FOR EXPLICIT DATA READ
   // Use Explicit MSG block to Read data from the SpectraLink.
   // *******************************************************************************************************************************************************************************
   3: XIC(Start_ReadMSG)[ONS(msgRead_ONS) MOVE(Test_Read_Att,msgRead_spLink.Instance) MSG(msgRead_spLink) ,[XIC(msgRead_spLink.DN) ,XIC(msgRead_spLink.ER) ] MOVE(Test_Read_Data,Read_Temp) OTU(Start_ReadMSG) ];
   // *****************************************************************************************************************************************************
   // The following five Rungs are to detect if SpectraLink is online or not, if SpectraLink is online, the value return from GSV will be 16384,
   // otherwise, SpectraLink will be offline
   // *****************************************************************************************************************************************************
   4: GSV(Module,SpectraLink,EntryStatus,i_splink_1_Comm);
   5: NE(i_splink_1_Comm,16384)OTL(spLink_HMI.b_r_LostComm);
   6: EQ(i_splink_1_Comm,16384)TON(tm_spLink_CommStarting,?,?);
   7: XIC(tm_spLink_CommStarting.DN)OTU(spLink_HMI.b_r_LostComm);
   8: XIC(spLink_HMI.b_r_LostComm)ONS(splink_LostComm_ONS)ADD(1,splink_CommLost_cnt,splink_CommLost_cnt);
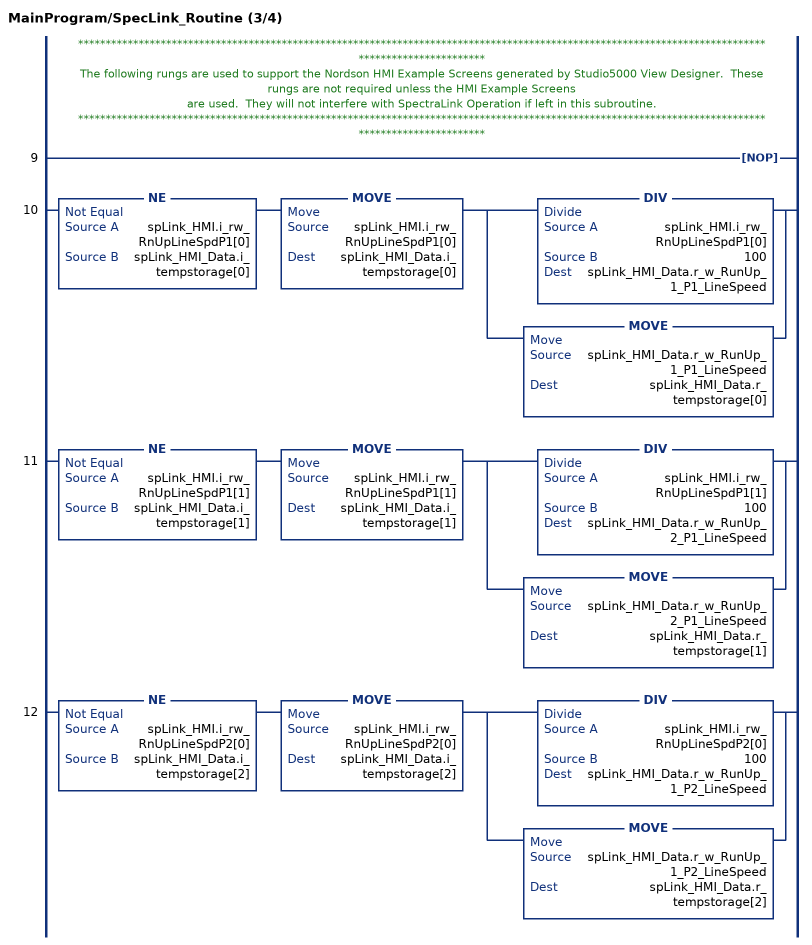
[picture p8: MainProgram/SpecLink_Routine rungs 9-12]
   // ****************************************************************************************************************************************************
   // The following rungs are used to support the Nordson HMI Example Screens generated by Studio5000 View Designer.  These rungs are not required unless the HMI Example Screens
   // are used.  They will not interfere with SpectraLink Operation if left in this subroutine.
   // ****************************************************************************************************************************************************
   9: NOP();
   10: NE(spLink_HMI.i_rw_RnUpLineSpdP1[0],spLink_HMI_Data.i_tempstorage[0])MOVE(spLink_HMI.i_rw_RnUpLineSpdP1[0],spLink_HMI_Data.i_tempstorage[0])[DIV(spLink_HMI.i_rw_RnUpLineSpdP1[0],100,spLink_HMI_Data.r_w_RunUp_1_P1_LineSpeed) ,MOVE(spLink_HMI_Data.r_w_RunUp_1_P1_LineSpeed,spLink_HMI_Data.r_tempstorage[0]) ];
   11: NE(spLink_HMI.i_rw_RnUpLineSpdP1[1],spLink_HMI_Data.i_tempstorage[1])MOVE(spLink_HMI.i_rw_RnUpLineSpdP1[1],spLink_HMI_Data.i_tempstorage[1])[DIV(spLink_HMI.i_rw_RnUpLineSpdP1[1],100,spLink_HMI_Data.r_w_RunUp_2_P1_LineSpeed) ,MOVE(spLink_HMI_Data.r_w_RunUp_2_P1_LineSpeed,spLink_HMI_Data.r_tempstorage[1]) ];
   12: NE(spLink_HMI.i_rw_RnUpLineSpdP2[0],spLink_HMI_Data.i_tempstorage[2])MOVE(spLink_HMI.i_rw_RnUpLineSpdP2[0],spLink_HMI_Data.i_tempstorage[2])[DIV(spLink_HMI.i_rw_RnUpLineSpdP2[0],100,spLink_HMI_Data.r_w_RunUp_1_P2_LineSpeed) ,MOVE(spLink_HMI_Data.r_w_RunUp_1_P2_LineSpeed,spLink_HMI_Data.r_tempstorage[2]) ];
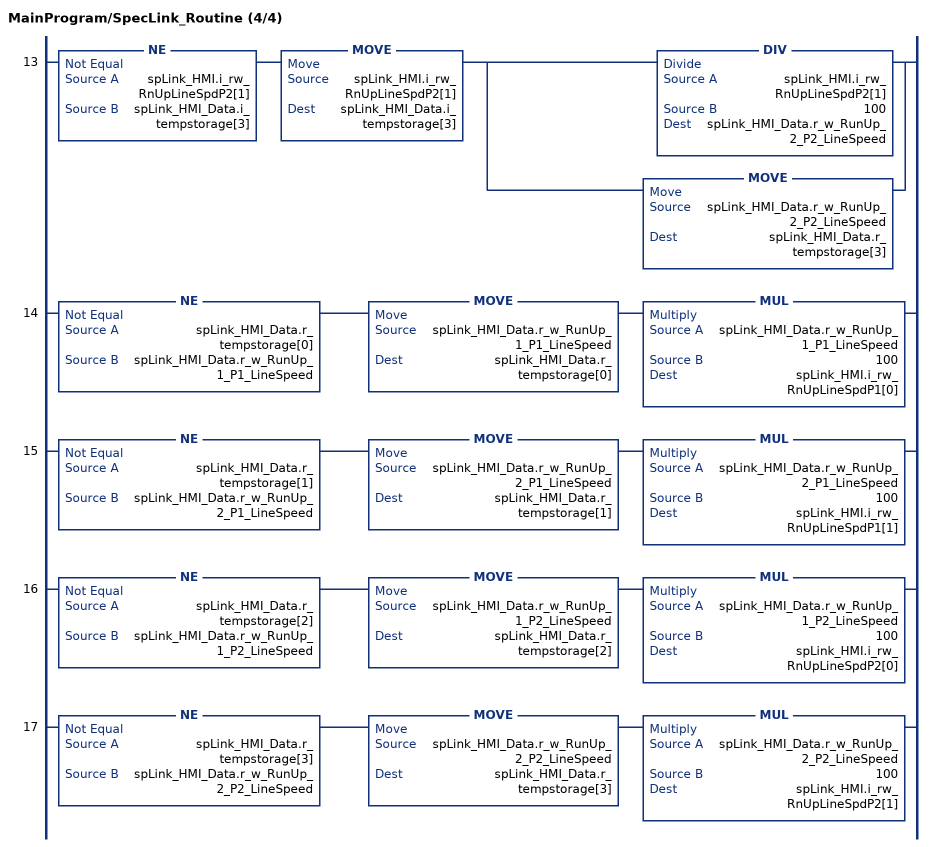
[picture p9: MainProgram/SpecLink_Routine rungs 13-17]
   13: NE(spLink_HMI.i_rw_RnUpLineSpdP2[1],spLink_HMI_Data.i_tempstorage[3])MOVE(spLink_HMI.i_rw_RnUpLineSpdP2[1],spLink_HMI_Data.i_tempstorage[3])[DIV(spLink_HMI.i_rw_RnUpLineSpdP2[1],100,spLink_HMI_Data.r_w_RunUp_2_P2_LineSpeed) ,MOVE(spLink_HMI_Data.r_w_RunUp_2_P2_LineSpeed,spLink_HMI_Data.r_tempstorage[3]) ];
   14: NE(spLink_HMI_Data.r_tempstorage[0],spLink_HMI_Data.r_w_RunUp_1_P1_LineSpeed)MOVE(spLink_HMI_Data.r_w_RunUp_1_P1_LineSpeed,spLink_HMI_Data.r_tempstorage[0])MUL(spLink_HMI_Data.r_w_RunUp_1_P1_LineSpeed,100,spLink_HMI.i_rw_RnUpLineSpdP1[0]);
   15: NE(spLink_HMI_Data.r_tempstorage[1],spLink_HMI_Data.r_w_RunUp_2_P1_LineSpeed)MOVE(spLink_HMI_Data.r_w_RunUp_2_P1_LineSpeed,spLink_HMI_Data.r_tempstorage[1])MUL(spLink_HMI_Data.r_w_RunUp_2_P1_LineSpeed,100,spLink_HMI.i_rw_RnUpLineSpdP1[1]);
   16: NE(spLink_HMI_Data.r_tempstorage[2],spLink_HMI_Data.r_w_RunUp_1_P2_LineSpeed)MOVE(spLink_HMI_Data.r_w_RunUp_1_P2_LineSpeed,spLink_HMI_Data.r_tempstorage[2])MUL(spLink_HMI_Data.r_w_RunUp_1_P2_LineSpeed,100,spLink_HMI.i_rw_RnUpLineSpdP2[0]);
   17: NE(spLink_HMI_Data.r_tempstorage[3],spLink_HMI_Data.r_w_RunUp_2_P2_LineSpeed)MOVE(spLink_HMI_Data.r_w_RunUp_2_P2_LineSpeed,spLink_HMI_Data.r_tempstorage[3])MUL(spLink_HMI_Data.r_w_RunUp_2_P2_LineSpeed,100,spLink_HMI.i_rw_RnUpLineSpdP2[1]);
END_ROUTINE
END_PROGRAM
